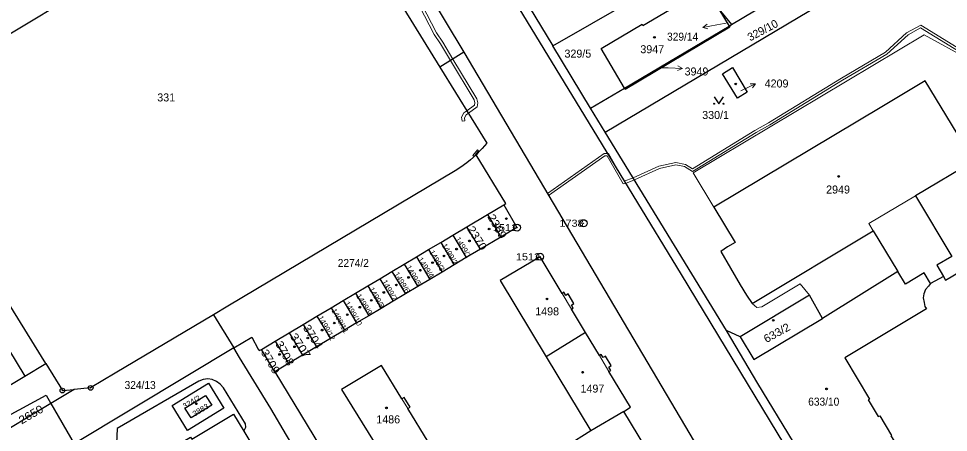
# Model space of a CAD drawing. Extents: x -679733 to -673243, y -1075091 to -1066557.
# Drawn here: x -676019.9 to -675822.4, y -1072340.3 to -1072252.4 of the extents above; entities that cross this region are included whole.
import ezdxf
from ezdxf.enums import TextEntityAlignment as Align

# ---------------------------------------------------------------- set-up
doc = ezdxf.new("R2010")
doc.units = 0
doc.header["$LTSCALE"] = 0.68
for name, color, linetype, lineweight in [('1', 7, 'Continuous', 25), ('13', 7, 'Continuous', 13), ('3', 7, 'Continuous', 25), ('4', 7, 'Continuous', 13), ('5', 7, 'Continuous', 25), ('7', 7, 'Continuous', 13), ('8', 7, 'Continuous', 25)]:
    doc.layers.add(name, color=color, linetype=linetype, lineweight=lineweight)
doc.layers.add('2', color=7, linetype='Continuous')

msp = doc.modelspace()

# ---------------------------------------------------------------- linework, layer by layer
at = {"layer": '1'}
for p, q in [((-675963.46, -1072209.2), (-675930.36, -1072262.74)), ((-675914.5, -1072244.76), (-675906.36, -1072258.16)), ((-675895.24, -1072276.53), (-675845.76, -1072247.06)), ((-675871.11, -1072250.38), (-675868.96, -1072253.98)), ((-675868.96, -1072253.98), (-675868.44, -1072253.67)), ((-675891.17, -1072267.15), (-675868.96, -1072253.98)), ((-675925.29, -1072259.54), (-675930.36, -1072262.74)), ((-675898.38, -1072271.42), (-675891.17, -1072267.15)), ((-675920.25, -1072294.02), (-675917.44, -1072298.8)), ((-675921.77, -1072301.38), (-675924.63, -1072296.63)), ((-675927.62, -1072298.41), (-675924.78, -1072303.18)), ((-675930.2, -1072299.94), (-675927.36, -1072304.71)), ((-675935.36, -1072303.02), (-675932.52, -1072307.79)), ((-675932.78, -1072301.48), (-675929.93, -1072306.25)), ((-675937.94, -1072304.56), (-675935.1, -1072309.33)), ((-675940.56, -1072306.12), (-675937.71, -1072310.89)), ((-675943.13, -1072307.65), (-675940.29, -1072312.42)), ((-675823.39, -1072307.22), (-675826.14, -1072308.69)), ((-675948.33, -1072310.75), (-675945.49, -1072315.52)), ((-675945.72, -1072309.2), (-675942.88, -1072313.97)), ((-675950.91, -1072312.29), (-675948.07, -1072317.06)), ((-675953.49, -1072313.83), (-675950.65, -1072318.6)), ((-675978.49, -1072315.33), (-675974.15, -1072322.36)), ((-675956.49, -1072315.61), (-675953.65, -1072320.38)), ((-675959.44, -1072317.39), (-675956.62, -1072322.13)), ((-675866.56, -1072320.02), (-675869.49, -1072318.68)), ((-675962.41, -1072319.16), (-675959.58, -1072323.9)), ((-675965.47, -1072327.41), (-675968.29, -1072322.72)), ((-675965.37, -1072320.93), (-675962.55, -1072325.67)), ((-676013.03, -1072334.17), (-676021.95, -1072339.58))]:
    msp.add_line(p, q, dxfattribs=at)
for points in [[(-675990.34, -1072122.74), (-675965.06, -1072164.5), (-675944.22, -1072198.66), (-675920.45, -1072238.88), (-675899.68, -1072273.04), (-675879.13, -1072306.74), (-675849.47, -1072355.79), (-675790.19, -1072454.14)], [(-675957.46, -1072205.54), (-675947.66, -1072221.89), (-675933.02, -1072246.64), (-675925.29, -1072259.54)], [(-675906.36, -1072258.16), (-675881.04, -1072243.59), (-675878.25, -1072241.39), (-675880.45, -1072238.71), (-675886.22, -1072231.53), (-675888.81, -1072228.27), (-675895.05, -1072232.27), (-675903.06, -1072237.41)], [(-676014.12, -1072325.69), (-676057.08, -1072256.19), (-676055.87, -1072255.44), (-676066.37, -1072237.96), (-676068.07, -1072234.95), (-676073.26, -1072238.04), (-676072.64, -1072239.08)], [(-675891.17, -1072267.15), (-675896.13, -1072258.79), (-675887.39, -1072253.59), (-675887.24, -1072253.85), (-675874.39, -1072246.25), (-675874.93, -1072245.59), (-675878.25, -1072241.39)], [(-675874.39, -1072246.25), (-675873.79, -1072245.89), (-675871.11, -1072250.38), (-675868.44, -1072253.67), (-675853.09, -1072244.45)], [(-675868.96, -1072253.98), (-675868.81, -1072254.23), (-675891, -1072267.43), (-675891.17, -1072267.15)], [(-676061.63, -1072257.37), (-676018.56, -1072328.36), (-676014.12, -1072325.69)], [(-675925.29, -1072259.54), (-675863.32, -1072364.28), (-675862.55, -1072365.47)], [(-675895.24, -1072276.53), (-675898.38, -1072271.42), (-675906.36, -1072258.16)], [(-675930.36, -1072262.74), (-675920.4, -1072278.85), (-675921.39, -1072279.99), (-675922.22, -1072280.85), (-675922.71, -1072281.32)], [(-675820.53, -1072276.81), (-675827.32, -1072265.63), (-675836.51, -1072271.12), (-675872.16, -1072292.47), (-675867.67, -1072299.93), (-675869.26, -1072300.87), (-675870.69, -1072301.87), (-675866.58, -1072308.98), (-675865.25, -1072311.17), (-675864.04, -1072312.9), (-675838.31, -1072297.5), (-675833.11, -1072306.11)], [(-675847.7, -1072354.86), (-675862.86, -1072329.89), (-675869.49, -1072318.68), (-675895.24, -1072276.53)], [(-675820.53, -1072276.81), (-675816.94, -1072282.72), (-675829.37, -1072290.05), (-675821.61, -1072302.95), (-675824.79, -1072304.77), (-675823.39, -1072307.22)], [(-675922.71, -1072281.32), (-675923.88, -1072282.38), (-675924.69, -1072283.04), (-675925.9, -1072283.94), (-675927.15, -1072284.77), (-675975.43, -1072313.51), (-675978.49, -1072315.33)], [(-675916.82, -1072291.97), (-675916.39, -1072291.71), (-675922.71, -1072281.32)], [(-675916.82, -1072291.97), (-675914.04, -1072296.77), (-675917.44, -1072298.8), (-675921.77, -1072301.38), (-675924.78, -1072303.18), (-675927.36, -1072304.71), (-675929.93, -1072306.25), (-675932.52, -1072307.79), (-675935.1, -1072309.33), (-675937.71, -1072310.89), (-675940.29, -1072312.42), (-675942.88, -1072313.97), (-675945.49, -1072315.52), (-675948.07, -1072317.06), (-675950.65, -1072318.6), (-675953.65, -1072320.38), (-675956.62, -1072322.13), (-675959.58, -1072323.9)], [(-675935.36, -1072303.02), (-675932.78, -1072301.48), (-675930.2, -1072299.94), (-675927.62, -1072298.41), (-675924.63, -1072296.63), (-675920.25, -1072294.02), (-675916.82, -1072291.97)], [(-675962.41, -1072319.16), (-675959.44, -1072317.39), (-675956.49, -1072315.61), (-675953.49, -1072313.83), (-675950.91, -1072312.29), (-675948.33, -1072310.75), (-675945.72, -1072309.2), (-675943.13, -1072307.65), (-675940.56, -1072306.12), (-675937.94, -1072304.56), (-675935.36, -1072303.02)], [(-675899.46, -1072319.05), (-675902.4, -1072314.14), (-675902.04, -1072313.92), (-675902.44, -1072313.25), (-675901.92, -1072312.94), (-675903.14, -1072310.9), (-675903.66, -1072311.21), (-675904.06, -1072310.54), (-675904.43, -1072310.77), (-675909.1, -1072302.99), (-675917.6, -1072308.02), (-675907.82, -1072324.25)], [(-675823.39, -1072307.22), (-675822.95, -1072308), (-675813.79, -1072302.53)], [(-675826.14, -1072308.69), (-675827.52, -1072306.39), (-675831.49, -1072308.79), (-675833.11, -1072306.11), (-675849.12, -1072316.14)], [(-675826.14, -1072308.69), (-675826.56, -1072309.22), (-675827.19, -1072309.93), (-675827.57, -1072310.88), (-675827.69, -1072311.75), (-675827.52, -1072312.73), (-675827.33, -1072313.58), (-675827.04, -1072314.06), (-675844.34, -1072324.49), (-675839.1, -1072333.23), (-675839.42, -1072333.42), (-675837.28, -1072336.95), (-675836.95, -1072336.77), (-675834.44, -1072340.93), (-675834.58, -1072341.01), (-675831.76, -1072345.39)], [(-675849.12, -1072316.14), (-675851.89, -1072311.17), (-675866.56, -1072320.02)], [(-675978.49, -1072315.33), (-675999.37, -1072327.75), (-676004.57, -1072330.85), (-676008.08, -1072331.18), (-676013.03, -1072334.17), (-676008.07, -1072342.7)], [(-675866.56, -1072320.02), (-675863.66, -1072324.84), (-675849.12, -1072316.14)], [(-675974.15, -1072322.36), (-675970.34, -1072320.08), (-675968.98, -1072322.6), (-675968.78, -1072322.93), (-675968.29, -1072322.72), (-675965.37, -1072320.93), (-675962.41, -1072319.16)], [(-675891.32, -1072335.84), (-675889.91, -1072334.94), (-675894.47, -1072327.35), (-675894.08, -1072327.12), (-675894.5, -1072326.42), (-675893.99, -1072326.11), (-675895.21, -1072324.09), (-675895.72, -1072324.4), (-675896.13, -1072323.73), (-675896.51, -1072323.96), (-675899.46, -1072319.05), (-675907.82, -1072324.25), (-675898.33, -1072340)], [(-675974.15, -1072322.36), (-675983.94, -1072328.23), (-676008.07, -1072342.7)], [(-675926.07, -1072402.03), (-675929.16, -1072396.81), (-675962.96, -1072340.92), (-675966.3, -1072335.23), (-675972.95, -1072324.36), (-675974.15, -1072322.36)], [(-675959.58, -1072323.9), (-675962.55, -1072325.67), (-675965.47, -1072327.41), (-675921.19, -1072400.45), (-675912.49, -1072394.77)], [(-676014.12, -1072325.69), (-676010.58, -1072331.41), (-676008.08, -1072331.18)], [(-675934.52, -1072343.3), (-675933.21, -1072342.55), (-675932.86, -1072342.34), (-675937.22, -1072335.22), (-675936.71, -1072334.91), (-675937.96, -1072332.87), (-675938.47, -1072333.19), (-675942.82, -1072326.1), (-675951.27, -1072331.19), (-675941.26, -1072347.38)], [(-676058.87, -1072361.92), (-676062.91, -1072364.37), (-676067.19, -1072357.62), (-676018.56, -1072328.36)], [(-675972.06, -1072340.04), (-675971.62, -1072339.22), (-675971.71, -1072338.5), (-675976.37, -1072330.82), (-675977.05, -1072330.09), (-675977.86, -1072329.49), (-675978.74, -1072329.04), (-675979.71, -1072328.91), (-675980.69, -1072329.04), (-675981.59, -1072329.44), (-675998.93, -1072339.45), (-675999.25, -1072345.84)], [(-676021.95, -1072339.58), (-676021.77, -1072338.78), (-676021.86, -1072337.78), (-676022.24, -1072336.86), (-676014.05, -1072332.41), (-676013.03, -1072334.17)], [(-675973.65, -1072363.72), (-675977.43, -1072357.37), (-675986.75, -1072362.96), (-675995.15, -1072348.94), (-675985.86, -1072343.37), (-675986.09, -1072342.93), (-675983.36, -1072341.3), (-675983.11, -1072341.72), (-675974.24, -1072336.41), (-675972.06, -1072340.04)], [(-675870.98, -1072369.33), (-675882.17, -1072350.91), (-675891.32, -1072335.84), (-675898.33, -1072340)], [(-675972.06, -1072340.04), (-675962.04, -1072356.7), (-675946.05, -1072383.28)], [(-675898.33, -1072340), (-675903.52, -1072343.25), (-675894.34, -1072358.45)]]:
    msp.add_lwpolyline(points, dxfattribs=at)
for points in [[(-676014.59, -1072240.96), (-676016.22, -1072238.25), (-676011.2, -1072235.2), (-676004.91, -1072245.51), (-676043.63, -1072268.84), (-676048.24, -1072261.29)], [(-675865.09, -1072268.02), (-675867.18, -1072269.28), (-675870.32, -1072264.15), (-675868.22, -1072262.8)], [(-675983.99, -1072339.91), (-675987.25, -1072334.57), (-675979.51, -1072329.85), (-675976.25, -1072335.19)], [(-675980.17, -1072332.49), (-675978.85, -1072334.51), (-675983.25, -1072337.22), (-675984.6, -1072335.19)]]:
    msp.add_lwpolyline(points, close=True, dxfattribs=at)
at = {"layer": '13'}
for points in [[(-675934.74, -1072249.75), (-675931.63, -1072255.76), (-675930.28, -1072257.75), (-675928.11, -1072261.32), (-675923.08, -1072269.66), (-675922.93, -1072270.31), (-675923.02, -1072270.82), (-675924.64, -1072271.99), (-675924.33, -1072272.49), (-675922.46, -1072271.16), (-675922.31, -1072270.29), (-675922.52, -1072269.44), (-675927.6, -1072261), (-675929.78, -1072257.41), (-675931.13, -1072255.44), (-675934.22, -1072249.43)], [(-675817.74, -1072260.25), (-675828.24, -1072253.77), (-675831.24, -1072255.45), (-675835.72, -1072259.56), (-675845.1, -1072265.09), (-675860.57, -1072274.52), (-675863.47, -1072276.18), (-675876.7, -1072284.31), (-675878.21, -1072283.37), (-675880.29, -1072282.99), (-675883.88, -1072283.75), (-675889.33, -1072286.21), (-675891.21, -1072286.93), (-675894.55, -1072281.07), (-675894.78, -1072281.07), (-675895.51, -1072281.05), (-675907.54, -1072289.55), (-675907.28, -1072289.98), (-675895.35, -1072281.55), (-675894.85, -1072281.57), (-675891.47, -1072287.47), (-675890.92, -1072287.41), (-675889.07, -1072286.64), (-675883.72, -1072284.23), (-675880.29, -1072283.49), (-675878.39, -1072283.85), (-675876.7, -1072284.89), (-675863.21, -1072276.62), (-675860.31, -1072274.96), (-675844.84, -1072265.51), (-675835.42, -1072259.96), (-675830.94, -1072255.85), (-675828.26, -1072254.35), (-675818, -1072260.67)]]:
    msp.add_lwpolyline(points, dxfattribs=at)
for points in [[(-675925.65, -1072274.22), (-675925.05, -1072274.14), (-675925.14, -1072273.47), (-675924.83, -1072272.85), (-675924.33, -1072272.49), (-675924.64, -1072271.99), (-675925.29, -1072272.45), (-675925.76, -1072273.37)], [(-675922.39, -1072280.25), (-675923.4, -1072281.5), (-675923.13, -1072281.71), (-675922.15, -1072280.47)]]:
    msp.add_lwpolyline(points, close=True, dxfattribs=at)
at = {"layer": '3'}
msp.add_lwpolyline([(-675872.12, -1072268.989), (-675871.12, -1072270.49), (-675870.12, -1072268.989)], dxfattribs=at)
for centre in [(-675872.12, -1072270.4895), (-675870.12, -1072270.4895)]:
    msp.add_circle(centre, 0.1, dxfattribs=at)
at = {"layer": '4'}
for p, q in [((-675876.6, -1072285.16), (-675827.48, -1072255.84)), ((-675827.48, -1072255.84), (-675805.81, -1072267.81)), ((-675872.16, -1072292.47), (-675876.6, -1072285.16)), ((-675829.37, -1072290.05), (-675839.26, -1072295.9)), ((-675839.26, -1072295.9), (-675838.31, -1072297.5)), ((-675853.83, -1072308.78), (-675861.97, -1072313.6)), ((-675851.89, -1072311.17), (-675853.83, -1072308.78)), ((-675904.43, -1072310.77), (-675902.4, -1072314.14)), ((-675863.05, -1072313.75), (-675864.04, -1072312.9)), ((-675861.97, -1072313.6), (-675863.05, -1072313.75)), ((-675896.51, -1072323.96), (-675894.47, -1072327.35)), ((-675938.47, -1072333.19), (-675937.22, -1072335.22))]:
    msp.add_line(p, q, dxfattribs=at)
at = {"layer": '5'}
for centre, radius in [((-675884.7968, -1072256.3792), 0.175), ((-675883.8346, -1072262.9894), 0.1172), ((-675867.5368, -1072266.2792), 0.175), ((-675845.6568, -1072285.9392), 0.175), ((-675916.2668, -1072294.8992), 0.175), ((-675919.9168, -1072297.1092), 0.175), ((-675924.1068, -1072299.6192), 0.175), ((-675929.5068, -1072302.8192), 0.175), ((-675926.8468, -1072301.3692), 0.175), ((-675931.9468, -1072304.2592), 0.175), ((-675934.5268, -1072305.8592), 0.175), ((-675939.6268, -1072308.9892), 0.175), ((-675937.0468, -1072307.3892), 0.175), ((-675942.2968, -1072310.5792), 0.175), ((-675944.9568, -1072312.2592), 0.175), ((-675907.6468, -1072311.9492), 0.175), ((-675947.3968, -1072313.7092), 0.175), ((-675950.0568, -1072315.3092), 0.175), ((-675859.5568, -1072316.4892), 0.175), ((-675955.4068, -1072318.5792), 0.175), ((-675952.8168, -1072317.0792), 0.175), ((-675958.4468, -1072320.2592), 0.175), ((-675961.2568, -1072322.1192), 0.175), ((-675964.4468, -1072323.7492), 0.175), ((-675900.0668, -1072327.5192), 0.175), ((-675848.2368, -1072331.0592), 0.175), ((-675982.1068, -1072334.2192), 0.175), ((-675941.7268, -1072335.0992), 0.175)]:
    msp.add_circle(centre, radius, dxfattribs=at)
at = {"layer": '7'}
for p, q in [((-675874.525, -1072254.261), (-675873.452, -1072254.58)), ((-675878.871, -1072262.985), (-675879.854, -1072262.449)), ((-675863.323, -1072266.244), (-675864.442, -1072266.233))]:
    msp.add_line(p, q, dxfattribs=at)
for points in [[(-675869.23, -1072253.32), (-675871.57, -1072253.74), (-675874.525, -1072254.261), (-675873.626, -1072253.594)], [(-675883.54, -1072262.83), (-675881.87, -1072262.88), (-675878.871, -1072262.985), (-675879.889, -1072263.45)], [(-675866.44, -1072267.76), (-675866.02, -1072267.56), (-675863.323, -1072266.244), (-675864.003, -1072267.134)]]:
    msp.add_lwpolyline(points, dxfattribs=at)
at = {"layer": '8'}
for centre, radius in [((-675899.86, -1072295.8698), 0.75), ((-675913.99, -1072296.7998), 0.75), ((-675913.99, -1072296.7998), 0.03), ((-675899.86, -1072295.8698), 0.03), ((-675909.1, -1072302.9898), 0.75), ((-675909.1, -1072302.9898), 0.03), ((-676004.57, -1072330.8499), 0.5), ((-676010.58, -1072331.4099), 0.5), ((-676010.58, -1072331.4099), 0.0303), ((-676004.57, -1072330.8499), 0.0303)]:
    msp.add_circle(centre, radius, dxfattribs=at)

# ---------------------------------------------------------------- texts
at = {"layer": '2'}
msp.add_text('329/10', height=1.7, rotation=28, dxfattribs=at).set_placement((-675861.4141, -1072255.6285), align=Align.CENTER)
at = {"layer": '2', "width": 0.95}
msp.add_text('329/14', height=1.7, dxfattribs=at).set_placement((-675875.52, -1072257.093), align=Align.RIGHT)
at = {"layer": '2'}
for s, p in [('329/5', (-675901.07, -1072260.69)), ('3947', (-675885.27, -1072259.759)), ('4209', (-675858.86, -1072267.04))]:
    msp.add_text(s, height=1.7, dxfattribs=at).set_placement(p, align=Align.CENTER)
for s, p in [('3949', (-675878.4, -1072264.483)), ('331', (-675990.42, -1072269.999)), ('330/1', (-675874.66, -1072273.729)), ('2949', (-675848.33, -1072289.56)), ('1498', (-675910.13, -1072315.44)), ('1497', (-675900.51, -1072331.85)), ('1486', (-675943.89, -1072338.39))]:
    msp.add_text(s, height=1.7, dxfattribs=at).set_placement(p)
for s, height, rotation, width, p in [('2369', 1.7, 300, 1.1, (-675920.336, -1072294.545)), ('2370', 1.7, 302, 1.1, (-675924.66, -1072297.12)), ('1499/1', 1.14, 301, 1.05, (-675927.138, -1072299.203)), ('1499/2', 1.14, 301, 1.05, (-675930.018, -1072300.613)), ('1499/4', 1.14, 303, 1.05, (-675935.138, -1072303.57)), ('1499/6', 1.14, 301, 1.05, (-675940.158, -1072306.643)), ('1499/9', 1.14, 302, 1.05, (-675948.223, -1072311.322)), ('3704', 1.7, 302, 1.1, (-675959.55, -1072318.06)), ('633/2', 1.7, 29, 1.05, (-675861.007, -1072321.353)), ('3707', 1.7, 303, 1.15, (-675962.302, -1072319.912)), ('3709', 1.7, 300, 1.1, (-675968.496, -1072323.275)), ('3708', 1.7, 299, 1.1, (-675965.413, -1072321.472)), ('324/2', 1.14, 30, 1.05, (-675984.595, -1072335.323)), ('2650', 1.7, 30, 1.1, (-676019.235, -1072338.626)), ('3883', 1.14, 31, 1.1, (-675982.526, -1072336.978))]:
    msp.add_text(s, height=height, rotation=rotation, dxfattribs=dict(at, width=width)).set_placement(p)
for s, rotation, p in [('1499/3', 300, (-675932.673, -1072302.005)), ('1499/5', 300, (-675937.613, -1072305.204)), ('1499/7', 299, (-675942.718, -1072308.276)), ('1499/8', 300, (-675945.473, -1072309.875)), ('1499/10', 300, (-675950.673, -1072312.885)), ('1499/11', 299, (-675953.458, -1072314.396)), ('1499/12', 299, (-675956.318, -1072315.916))]:
    msp.add_text(s, height=1.14, rotation=rotation, dxfattribs=at).set_placement(p)
at = {"layer": '2', "width": 0.95}
for s, p in [('2274/2', (-675952.08, -1072305.17)), ('324/13', (-675997.36, -1072331.09)), ('633/10', (-675852.14, -1072334.62))]:
    msp.add_text(s, height=1.7, dxfattribs=at).set_placement(p)
at = {"layer": '8', "width": 1.15}
for s, p in [('1738', (-675899.859, -1072296.62)), ('1511', (-675913.989, -1072297.55)), ('1512', (-675909.099, -1072303.74))]:
    msp.add_text(s, height=1.5, dxfattribs=at).set_placement(p, align=Align.RIGHT)

doc.saveas('drawing.dxf')
